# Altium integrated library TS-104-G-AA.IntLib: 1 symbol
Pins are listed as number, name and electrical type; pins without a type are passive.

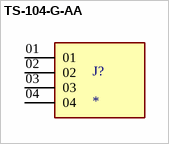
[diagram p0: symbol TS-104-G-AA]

## TS-104-G-AA
designator J?
MF: Samtec Inc.; MP: TS-104-G-AA
footprint SAMTEC_TS-104-G-AA
pins: 01, 02, 03, 04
